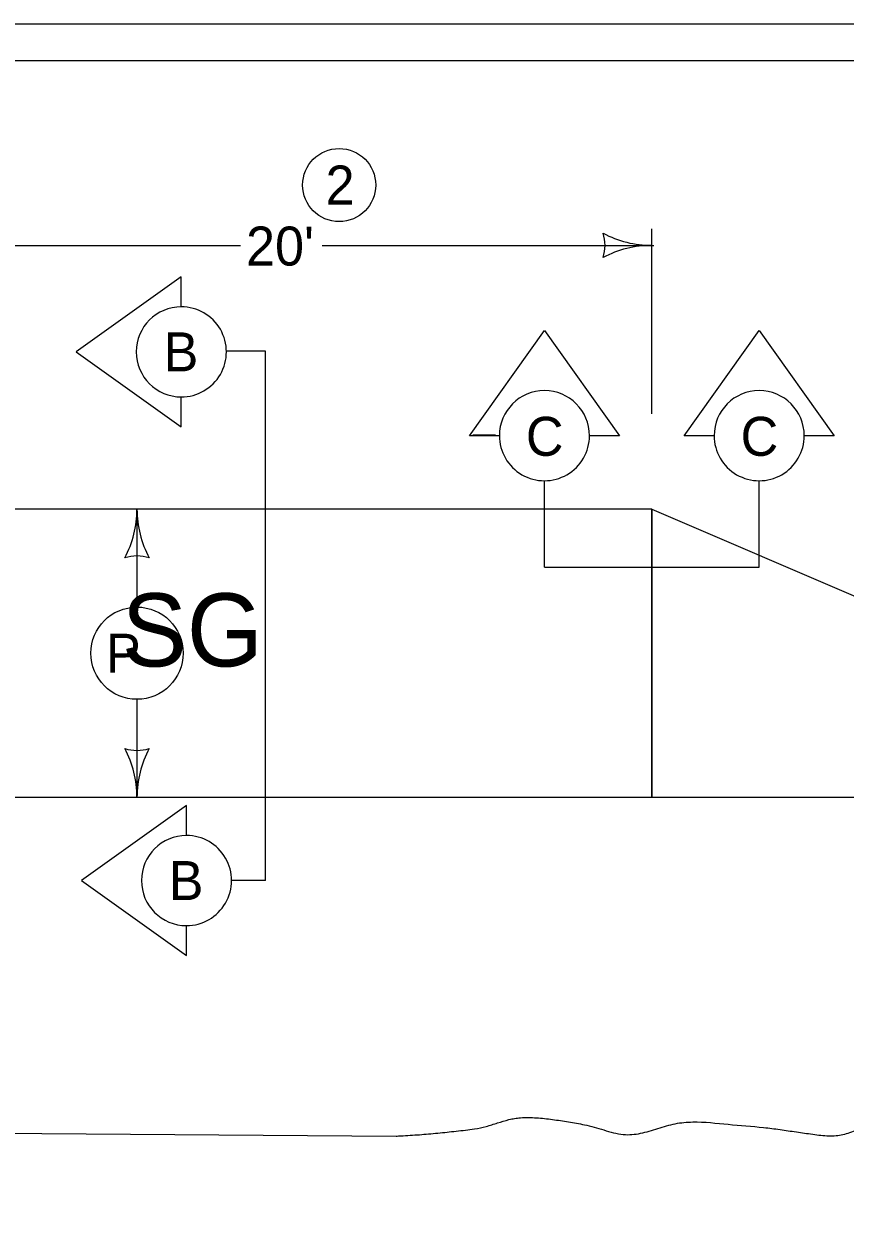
# Model space of a CAD drawing. Extents: x 9538 to 81668, y 7600 to 11751.
# Drawn here: x 15143.2 to 15480.1, y 9452.3 to 9944 of the extents above; entities that cross this region are included whole.
import ezdxf

# ---------------------------------------------------------------- set-up
doc = ezdxf.new("R2010")
doc.units = 0
for name, color, linetype in [('Default', 7, 'Continuous'), ('DsnShtMinorGrid13', 7, 'Continuous'), ('DsnShtMinorGrid16', 7, 'Continuous'), ('dsnStdDimension', 7, 'Continuous'), ('dsnStdPattern', 7, 'Continuous'), ('dsnStdShading', 7, 'Continuous'), ('dsnStdTable', 7, 'Continuous')]:
    doc.layers.add(name, color=color, linetype=linetype)

msp = doc.modelspace()

# ---------------------------------------------------------------- linework, layer by layer
at = {"layer": 'Default'}
msp.add_lwpolyline([(13732.53, 9944.02), (16867.53, 9944.02), (16867.53, 7924.02), (13732.53, 7924.02)], close=True, dxfattribs=at)
at = {"layer": 'DsnShtMinorGrid13'}
msp.add_circle((15272.55, 9877.91), 15, dxfattribs=at)
at = {"layer": 'DsnShtMinorGrid16'}
for p, q in [((15400.84, 9744.89), (15096.1, 9744.89)), ((15400.84, 9626.66), (15400.84, 9744.89)), ((15096.1, 9626.66), (15400.84, 9626.66))]:
    msp.add_line(p, q, dxfattribs=at)
msp.add_circle((15189.6, 9685.77), 18.93, dxfattribs=at)
at = {"layer": 'dsnStdDimension'}
for p, q in [((15400.84, 9783.96), (15400.84, 9859.98)), ((15096.1, 9853.15), (15232.1, 9853.15)), ((15265.62, 9853.15), (15401.62, 9853.15)), ((15189.6, 9744.89), (15189.6, 9704.71)), ((15189.6, 9666.84), (15189.6, 9626.66))]:
    msp.add_line(p, q, dxfattribs=at)
msp.add_circle((15189.6, 9685.77), 18.93, dxfattribs=at)
for centre, radius, start, end in [((15365.21, 9853.15), 16.42, 342.2666, 17.7333), ((15400.84, 9895.65), 42.5, 241.9275, 270), ((15400.84, 9810.65), 42.5, 90, 118.0725), ((15147.1, 9744.89), 42.5, 331.9275, 0), ((15232.1, 9744.89), 42.5, 180, 208.0725), ((15189.6, 9709.25), 16.42, 72.2666, 107.7334), ((15189.6, 9662.29), 16.42, 252.2666, 287.7333), ((15147.1, 9626.66), 42.5, 360, 28.0725), ((15232.1, 9626.66), 42.5, 151.9275, 180)]:
    msp.add_arc(centre, radius, start, end, dxfattribs=at)
at = {"layer": 'dsnStdPattern'}
for p, q in [((15242.36, 9809.76), (15226.58, 9809.76)), ((15242.36, 9592.47), (15242.36, 9809.76)), ((15356.79, 9721.12), (15356.79, 9756.56)), ((15444.89, 9721.12), (15444.89, 9756.56)), ((15356.79, 9721.12), (15444.89, 9721.12)), ((15242.36, 9592.47), (15228.4, 9592.47))]:
    msp.add_line(p, q, dxfattribs=at)
for points in [[(15207.79, 9827.94), (15207.79, 9840.26), (15164.66, 9809.45), (15207.79, 9778.64), (15207.79, 9790.97)], [(15338.31, 9775.05), (15325.98, 9775.05), (15356.79, 9818.18), (15387.6, 9775.05), (15375.28, 9775.05)], [(15426.41, 9775.05), (15414.08, 9775.05), (15444.89, 9818.18), (15475.7, 9775.05), (15463.38, 9775.05)], [(15209.92, 9610.96), (15209.92, 9623.28), (15166.78, 9592.47), (15209.92, 9561.66), (15209.92, 9573.99)]]:
    msp.add_lwpolyline(points, dxfattribs=at)
for centre, start, end in [((15207.79, 9809.45), 90.0008, 269.9992), ((15207.79, 9809.45), 269.9992, 90.0008), ((15356.79, 9775.05), 0.0008, 179.9992), ((15444.89, 9775.05), 0.0008, 179.9992), ((15356.79, 9775.05), 179.9992, 0.0008), ((15444.89, 9775.05), 179.9992, 0.0008), ((15209.92, 9592.47), 90.0008, 269.9992), ((15209.92, 9592.47), 269.9992, 90.0008)]:
    msp.add_arc(centre, 18.49, start, end, dxfattribs=at)
at = {"layer": 'dsnStdShading'}
msp.add_line((13747.53, 9929.02), (16843.22, 9929.02), dxfattribs=at)
at = {"layer": 'dsnStdTable'}
for p, q in [((15336.7, 9775.2), (15327.46, 9775.28)), ((15336.7, 9775.2), (15330.1, 9775.26)), ((15400.84, 9744.89), (15096.1, 9744.89)), ((15400.84, 9744.89), (15400.84, 9626.66)), ((15400.84, 9744.89), (15504.88, 9700.29)), ((14152, 9626.66), (15577.73, 9626.66)), ((14966.69, 9490.03), (15295.89, 9487.58))]:
    msp.add_line(p, q, dxfattribs=at)
msp.add_spline([(15295.89, 9487.58), (15297.89, 9487.69), (15305.46, 9488.17), (15313.03, 9488.83), (15320.58, 9489.63), (15328.11, 9490.54), (15332.86, 9491.54), (15337.54, 9492.98), (15342.21, 9494.34), (15344.56, 9494.83), (15346.93, 9495.1), (15353.47, 9495.09), (15360.06, 9494.43), (15366.64, 9493.39), (15373.16, 9492.25), (15377.17, 9491.31), (15381.14, 9490.11), (15385.12, 9488.98), (15389.13, 9488.26), (15392.67, 9488.23), (15396.22, 9488.73), (15403.33, 9490.66), (15410.47, 9492.67), (15417.64, 9493.39), (15432.17, 9492.42), (15446.72, 9491.11), (15453.44, 9490.29), (15460.14, 9489.3), (15466.84, 9488.36), (15473.52, 9487.69), (15479.27, 9488.25), (15484.95, 9490.08), (15490.61, 9492.13), (15496.33, 9493.39), (15503.83, 9493.9), (15511.43, 9494.03), (15522.82, 9493.33), (15526.55, 9492.82), (15533.57, 9491), (15540.47, 9488.43), (15547.39, 9486.06), (15554.49, 9484.83), (15575.6, 9483.83)], degree=3, dxfattribs=at)

# ---------------------------------------------------------------- texts
at = {"layer": 'DsnShtMinorGrid13'}
msp.add_text('2', height=16, dxfattribs=at).set_placement((15266.97, 9869.91))
at = {"layer": 'dsnStdDimension'}
for s, height, p in [("20'", 16, (15234.34, 9844.87)), ('SG', 30, (15183.31, 9680.33)), ('P', 16, (15176.88, 9677.77))]:
    msp.add_text(s, height=height, dxfattribs=at).set_placement(p)
at = {"layer": 'dsnStdPattern'}
for s, p in [('B', (15200.52, 9801.45)), ('C', (15349.16, 9766.78)), ('C', (15437.27, 9766.78)), ('B', (15202.61, 9584.47))]:
    msp.add_text(s, height=16, dxfattribs=at).set_placement(p)

doc.saveas('drawing.dxf')
